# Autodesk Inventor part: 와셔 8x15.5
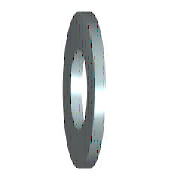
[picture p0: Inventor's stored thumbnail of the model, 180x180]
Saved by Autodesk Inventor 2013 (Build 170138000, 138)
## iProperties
Created: 2012-02
Part Number: 와셔 8x15.5
Material: 강철, 연강
Description: 평면 와셔
Document SubType Name: Modeling
Standard: KS B 1326
Designer: mduedu
Standards Organization: KS
Language: ko-KR
Size Designation: 8x15.5
Categories: <MemberInstance><Categories><Category DisplayName="조임쇠" InternalName="e4da775c-781d-43d5-af7c-5136215cf5a6" Mnemonic="FSTN"><Category DisplayName="와셔" InternalN
Density: 7.86 g/cm^3
Mass: 1.67606 g
Surface Area: 3.86683 cm^2
Volume: 0.213239 cm^3
IsCustomPart: 1
Author: mduedu
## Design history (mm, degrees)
sketch "스케치"
  geometry: C1 r 7.75 at (0, 0); C2 r 4.2 at (0, 0); 1 further point
  constraints: 2 centre point, 2 coincident
  dimensions: "d0" = 8.4 diameter of C2 (= SD1); "d1" = 15.5 diameter of C1 (= SD2)
extrude "본체" new body sketch "스케치" distance "d2" = 1.6 (= SD); taper "d3" = 0 deg
workaxis "Work Axis1"
workplane "Work Plane1"
body "Solid1"
other parameters: "SD1" = 8.4 [user parameter; used in 1 equation term], "SD2" = 15.5 [user parameter; used in 1 equation term], "SD" = 1.6 [user parameter; used in 1 equation term], "d4" = 0, "d5" = 0, "d6" = 0, "d7" = 0, "NND" = 8 [user parameter]
